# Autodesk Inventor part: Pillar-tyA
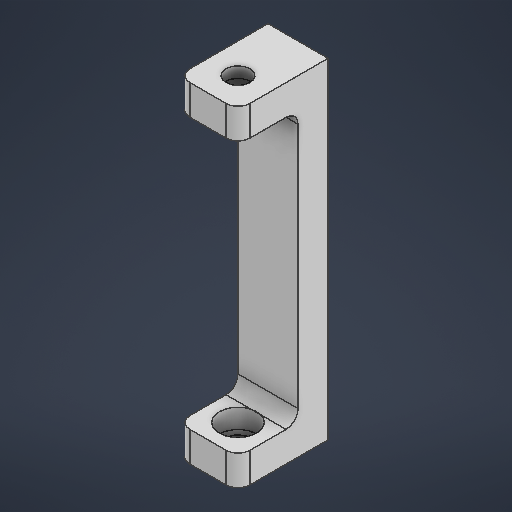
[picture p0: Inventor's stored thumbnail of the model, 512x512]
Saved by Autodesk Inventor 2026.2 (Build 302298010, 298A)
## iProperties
Created: 2026-05
Part Number: Pillar-tyA
Material: 일반
Document SubType Name: Modeling
Designer: work
Density: 1 g/cm^3
Appearance: 기본값
Author: work
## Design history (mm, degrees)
sketch "스케치1"
  geometry: L1 (-5, 5)-(5, 5); L2 (5, 5)-(5, -5); L3 (5, -5)-(-5, -5); L4 (-5, -5)-(-5, 5); L5 (-5, 5)-(5, -5); L6 (5, 5)-(-5, -5); L7 (5, -5)-(-5, -5); L8 (-5, -5)-(-5, -11); L9 (-5, -11)-(5, -11); L10 (5, -11)-(5, -5); C1 r 2 at (0, 0); C2 r 3.1 at (4, 4); 3 further points
  constraints: 20 end point, 4 parallel, 2 centre point, 2 horizontal, 2 midpoint, 2 perpendicular, 1 coincident
  dimensions: "d0" = 4 diameter of C1; "d1" = 10 distance of L2.end L3.end; "d2" = 10 distance of L1.end L2.end; "d3" = 6 distance of L9.end L2.end; "d4" = 6.2 diameter of C2; "d5" = 4 horizontal distance of point (0, 0) C2.centre; "d6" = 4 horizontal distance of C2.centre point (0, 0)
extrude "돌출1" new body sketch "스케치1" distance "d7" = 5; taper "d8" = 0 deg
extrude "돌출2" join sketch "스케치1" distance "d9" = 50; taper "d10" = 0 deg
sketch "스케치2"
  geometry: L1 (5, 5)-(-5, 5) reference; L2 (-5, 5)-(-5, -5) reference; L3 (-5, -5)-(5, -5) reference; L4 (5, -5)-(5, 5) reference; L5 (-5, 5)-(5, 5) reference; L6 (5, 5)-(5, 11) reference; L7 (5, 11)-(-5, 11) reference; L8 (-5, 11)-(-5, 5) reference; L9 (-5, -1.066)-(-5, -5); L10 (-5, -5)-(-1.066, -5); C1 r 2 at (0, 0) reference; 5 further points
  constraints: 4 end point, 1 perpendicular, 1 vertical
extrude "돌출3" join sketch "스케치2" distance "d11" = 5; taper "d12" = 0 deg
sketch "스케치3"
  geometry: C1 r 2 at (0, 0) reference; 2 further points
  constraints: 1 coincident
hole "구멍1" sketch "스케치3" at (0, 0) diameter "d13" = 4; stored, may be unused: countersink angle "d17" = 90 deg, drill point angle "d19" = 118 deg; dims "d14" = 6, "d15" = 6.2, "d16" = 3.2, "d18" = 8
fillet "모깎기1" dims "d20" = 2
chamfer "모따기1" distance "d21" = 1; stored, may be unused: second distance "d22" = 2, angle "d23" = 45 deg
sketch "스케치4"
  geometry: C1 r 2 at (0, 0) reference; 2 further points
  constraints: 1 coincident
hole "구멍2" sketch "스케치4" at (0, 0) diameter "d24" = 4; stored, may be unused: countersink angle "d28" = 90 deg, drill point angle "d30" = 118 deg; dims "d25" = 6, "d26" = 6.2, "d27" = 3.2, "d29" = 8
node "솔리드1"
node "투영된 루프1"
node "투영된 루프2"
feature "A9D066F2-1C7D-4E18-AEED-F7BC21143FA4" dims "d13" = 4, "d14" = 6, "d15" = 6.2, "d16" = 3.2, "d17" = 90 deg, "d18" = 8, "d19" = 118 deg
